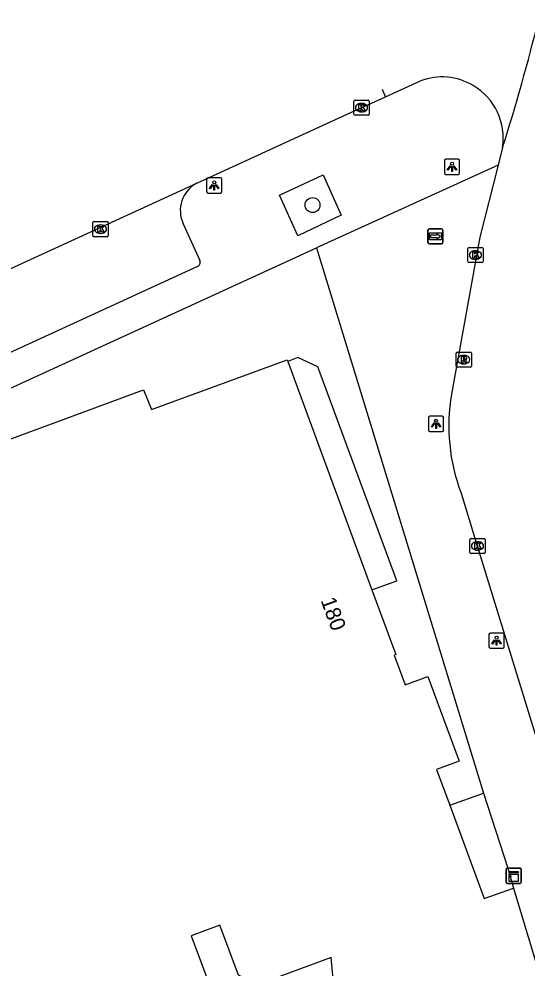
# Model space of a CAD drawing. Extents: x 160806 to 161707, y 383697 to 384148.
# Drawn here: x 161067.6 to 161101, y 383971.5 to 384033.9 of the extents above; entities that cross this region are included whole.
import ezdxf

# ---------------------------------------------------------------- set-up
doc = ezdxf.new("R2010")
doc.units = 0
for name, color, linetype in [('IMGEO_Boom', 7, 'Continuous'), ('IMGEO_Fietspad_gesloten', 7, 'Continuous'), ('IMGEO_Kast', 7, 'Continuous'), ('IMGEO_Kolk', 7, 'Continuous'), ('IMGEO_Lichtpunt', 7, 'Continuous'), ('IMGEO_Pand', 7, 'Continuous'), ('IMGEO_Pand_nummerreeks', 7, 'Continuous'), ('IMGEO_Pand_overbouw', 7, 'Continuous'), ('IMGEO_Rijbaan_lokaal_open', 7, 'Continuous'), ('IMGEO_Rioolput', 7, 'Continuous'), ('IMGEO_Voetpad_open', 7, 'Continuous'), ('IMGEO_Wegwijzer', 7, 'Continuous')]:
    doc.layers.add(name, color=color, linetype=linetype)

msp = doc.modelspace()

# ---------------------------------------------------------------- linework, layer by layer
at = {"layer": 'IMGEO_Boom'}
msp.add_circle((161086.888, 384021.682), 0.489, dxfattribs=at)
at = {"layer": 'IMGEO_Fietspad_gesloten'}
for points in [[(161099.383, 384025.462), (161099.091, 384024.316)], [(161099.091, 384024.316), (161097.884, 384019.582), (161096.025, 384009.243)], [(161096.658, 384002.717), (161097.481, 384000.05), (161112.041, 383952.737)]]:
    msp.add_lwpolyline(points, dxfattribs=at)
msp.add_arc((161108.463, 384007.156), 12.612, 170.47348, 200.60685, dxfattribs=at)
at = {"layer": 'IMGEO_Kast'}
for p, q in [((161099.62, 383977.119), (161099.62, 383977.96)), ((161099.62, 383977.96), (161099.62, 383977.119)), ((161099.695, 383978.044), (161100.536, 383978.044)), ((161100.536, 383978.044), (161099.695, 383978.044)), ((161100.62, 383977.969), (161100.62, 383977.128)), ((161100.62, 383977.128), (161100.62, 383977.969)), ((161100.545, 383977.044), (161099.704, 383977.044)), ((161099.704, 383977.044), (161100.545, 383977.044))]:
    msp.add_line(p, q, dxfattribs=at)
for points in [[(161099.815, 383977.834), (161100.415, 383977.834), (161100.415, 383977.749), (161099.815, 383977.749), (161099.815, 383977.834)], [(161099.815, 383977.659), (161100.415, 383977.659), (161100.415, 383977.17), (161099.815, 383977.17), (161099.815, 383977.659)]]:
    msp.add_lwpolyline(points, dxfattribs=at)
msp.add_circle((161099.899, 383977.508), 0.0377, dxfattribs=at)
for centre, start, end in [((161099.698, 383977.966), 92.4484, 184.28452), ((161099.698, 383977.966), 92.4484, 184.28452), ((161100.542, 383977.966), 2.4484, 94.28452), ((161100.542, 383977.966), 2.4484, 94.28452), ((161099.698, 383977.122), 182.4484, 274.28452), ((161099.698, 383977.122), 182.4484, 274.28452), ((161100.542, 383977.122), 272.4484, 4.28452), ((161100.542, 383977.122), 272.4484, 4.28452)]:
    msp.add_arc(centre, 0.0779, start, end, dxfattribs=at)
at = {"layer": 'IMGEO_Kolk'}
for p, q in [((161089.612, 384027.668), (161089.612, 384028.52)), ((161089.687, 384028.594), (161090.539, 384028.594)), ((161090.1, 384028.374), (161090.125, 384028.374)), ((161090.613, 384028.52), (161090.613, 384027.668)), ((161090.123, 384027.814), (161090.098, 384027.814)), ((161090.539, 384027.594), (161089.687, 384027.594)), ((161072.447, 384019.675), (161072.447, 384020.527)), ((161072.522, 384020.601), (161073.374, 384020.601)), ((161072.935, 384020.381), (161072.96, 384020.381)), ((161073.448, 384020.527), (161073.448, 384019.675)), ((161072.958, 384019.821), (161072.933, 384019.821)), ((161073.374, 384019.601), (161072.522, 384019.601)), ((161097.106, 384017.971), (161097.106, 384018.823)), ((161097.181, 384018.897), (161098.033, 384018.897)), ((161097.594, 384018.677), (161097.619, 384018.677)), ((161098.107, 384018.823), (161098.107, 384017.971)), ((161098.033, 384017.897), (161097.181, 384017.897)), ((161097.617, 384018.117), (161097.592, 384018.117)), ((161097.239, 383998.825), (161097.239, 383999.677)), ((161097.314, 383999.751), (161098.166, 383999.751)), ((161098.24, 383999.677), (161098.24, 383998.825)), ((161097.727, 383999.531), (161097.752, 383999.531)), ((161098.166, 383998.751), (161097.314, 383998.751)), ((161097.75, 383998.971), (161097.725, 383998.971))]:
    msp.add_line(p, q, dxfattribs=at)
for points in [[(161089.612, 384027.668), (161089.612, 384028.52)], [(161089.687, 384028.594), (161090.539, 384028.594)], [(161090.613, 384028.52), (161090.613, 384027.668)], [(161089.933, 384028.294), (161090.056, 384028.294), (161090.056, 384028.143), (161090.186, 384028.294), (161090.35, 384028.294), (161090.204, 384028.143), (161090.357, 384027.894), (161090.205, 384027.894), (161090.12, 384028.058), (161090.056, 384027.991), (161090.056, 384027.894), (161089.933, 384027.894), (161089.933, 384028.294)], [(161090.539, 384027.594), (161089.687, 384027.594)], [(161072.447, 384019.675), (161072.447, 384020.527)], [(161072.522, 384020.601), (161073.374, 384020.601)], [(161072.768, 384020.301), (161072.891, 384020.301), (161072.891, 384020.15), (161073.021, 384020.301), (161073.185, 384020.301), (161073.039, 384020.15), (161073.192, 384019.901), (161073.04, 384019.901), (161072.955, 384020.065), (161072.891, 384019.998), (161072.891, 384019.901), (161072.768, 384019.901), (161072.768, 384020.301)], [(161073.448, 384020.527), (161073.448, 384019.675)], [(161073.374, 384019.601), (161072.522, 384019.601)], [(161097.106, 384017.971), (161097.106, 384018.823)], [(161097.181, 384018.897), (161098.033, 384018.897)], [(161097.427, 384018.597), (161097.55, 384018.597), (161097.55, 384018.446), (161097.68, 384018.597), (161097.844, 384018.597), (161097.698, 384018.446), (161097.851, 384018.197), (161097.699, 384018.197), (161097.614, 384018.361), (161097.55, 384018.294), (161097.55, 384018.197), (161097.427, 384018.197), (161097.427, 384018.597)], [(161098.107, 384018.823), (161098.107, 384017.971)], [(161098.033, 384017.897), (161097.181, 384017.897)], [(161097.239, 383998.825), (161097.239, 383999.677)], [(161097.314, 383999.751), (161098.166, 383999.751)], [(161098.24, 383999.677), (161098.24, 383998.825)], [(161097.56, 383999.451), (161097.683, 383999.451), (161097.683, 383999.3), (161097.813, 383999.451), (161097.977, 383999.451), (161097.831, 383999.3), (161097.984, 383999.051), (161097.832, 383999.051), (161097.747, 383999.215), (161097.683, 383999.148), (161097.683, 383999.051), (161097.56, 383999.051), (161097.56, 383999.451)], [(161098.166, 383998.751), (161097.314, 383998.751)]]:
    msp.add_lwpolyline(points, dxfattribs=at)
for centre, start, end in [((161089.689, 384028.518), 91.55205, 178.44795), ((161089.689, 384028.518), 91.55205, 178.44795), ((161090.537, 384028.518), 1.55205, 88.44795), ((161090.537, 384028.518), 1.55205, 88.44795), ((161089.689, 384027.67), 181.55205, 268.44795), ((161089.689, 384027.67), 181.55205, 268.44795), ((161090.537, 384027.67), 271.55205, 358.44795), ((161090.537, 384027.67), 271.55205, 358.44795), ((161072.524, 384020.525), 91.55205, 178.44795), ((161072.524, 384020.525), 91.55205, 178.44795), ((161073.372, 384020.525), 1.55205, 88.44795), ((161073.372, 384020.525), 1.55205, 88.44795), ((161072.524, 384019.677), 181.55205, 268.44795), ((161072.524, 384019.677), 181.55205, 268.44795), ((161073.372, 384019.677), 271.55205, 358.44795), ((161073.372, 384019.677), 271.55205, 358.44795), ((161097.183, 384018.821), 91.55205, 178.44795), ((161097.183, 384018.821), 91.55205, 178.44795), ((161098.031, 384018.821), 1.55205, 88.44795), ((161098.031, 384018.821), 1.55205, 88.44795), ((161097.183, 384017.973), 181.55205, 268.44795), ((161097.183, 384017.973), 181.55205, 268.44795), ((161098.031, 384017.973), 271.55205, 358.44795), ((161098.031, 384017.973), 271.55205, 358.44795), ((161097.316, 383999.675), 91.55205, 178.44795), ((161097.316, 383999.675), 91.55205, 178.44795), ((161098.164, 383999.675), 1.55205, 88.44795), ((161098.164, 383999.675), 1.55205, 88.44795), ((161097.316, 383998.827), 181.55205, 268.44795), ((161097.316, 383998.827), 181.55205, 268.44795), ((161098.164, 383998.827), 271.55205, 358.44795), ((161098.164, 383998.827), 271.55205, 358.44795)]:
    msp.add_arc(centre, 0.0765, start, end, dxfattribs=at)
for centre, major_axis, ratio, start_param, end_param in [((161090.099, 384028.094), (-0.387, 0.002), 0.722429, 4.712389, 7.853982), ((161090.124, 384028.094), (-0.39, 0.002), 0.717154, 1.570796, 4.712389), ((161072.934, 384020.101), (-0.387, 0.002), 0.722429, 4.712389, 7.853982), ((161072.959, 384020.101), (-0.39, 0.002), 0.717154, 1.570796, 4.712389), ((161097.593, 384018.397), (-0.387, 0.002), 0.722429, 4.712389, 7.853982), ((161097.618, 384018.397), (-0.39, 0.002), 0.717154, 1.570796, 4.712389), ((161097.726, 383999.251), (-0.387, 0.002), 0.722429, 4.712389, 7.853982), ((161097.751, 383999.251), (-0.39, 0.002), 0.717154, 1.570796, 4.712389)]:
    msp.add_ellipse(centre, major_axis=major_axis, ratio=ratio, start_param=start_param, end_param=end_param, dxfattribs=at)
at = {"layer": 'IMGEO_Lichtpunt'}
for p, q in [((161096.469, 384024.702), (161095.661, 384024.702)), ((161096.469, 384024.702), (161095.661, 384024.702)), ((161095.567, 384024.607), (161095.567, 384023.8)), ((161095.567, 384024.607), (161095.567, 384023.8)), ((161096.563, 384023.8), (161096.563, 384024.607)), ((161096.563, 384023.8), (161096.563, 384024.607)), ((161079.925, 384023.378), (161079.925, 384022.571)), ((161079.925, 384023.378), (161079.925, 384022.571)), ((161080.827, 384023.473), (161080.019, 384023.473)), ((161080.827, 384023.473), (161080.019, 384023.473)), ((161080.921, 384022.571), (161080.921, 384023.378)), ((161080.921, 384022.571), (161080.921, 384023.378)), ((161095.661, 384023.706), (161096.469, 384023.706)), ((161095.661, 384023.706), (161096.469, 384023.706)), ((161080.019, 384022.477), (161080.827, 384022.477)), ((161080.019, 384022.477), (161080.827, 384022.477)), ((161095.419, 384007.782), (161094.611, 384007.782)), ((161095.419, 384007.782), (161094.611, 384007.782)), ((161094.517, 384007.687), (161094.517, 384006.88)), ((161094.517, 384007.687), (161094.517, 384006.88)), ((161095.513, 384006.88), (161095.513, 384007.687)), ((161095.513, 384006.88), (161095.513, 384007.687)), ((161094.611, 384006.786), (161095.419, 384006.786)), ((161094.611, 384006.786), (161095.419, 384006.786)), ((161098.493, 383993.419), (161098.493, 383992.612)), ((161098.493, 383993.419), (161098.493, 383992.612)), ((161099.395, 383993.514), (161098.587, 383993.514)), ((161099.395, 383993.514), (161098.587, 383993.514)), ((161099.489, 383992.612), (161099.489, 383993.419)), ((161099.489, 383992.612), (161099.489, 383993.419)), ((161098.587, 383992.518), (161099.395, 383992.518)), ((161098.587, 383992.518), (161099.395, 383992.518))]:
    msp.add_line(p, q, dxfattribs=at)
for points in [[(161095.941, 384024.271), (161095.98, 384024.243), (161095.792, 384023.981), (161095.754, 384024.008), (161095.941, 384024.271)], [(161096.043, 384024.223), (161096.09, 384024.223), (161096.09, 384023.901), (161096.043, 384023.901), (161096.043, 384024.223)], [(161096.153, 384024.243), (161096.191, 384024.27), (161096.378, 384024.008), (161096.339, 384023.98), (161096.153, 384024.243)], [(161080.299, 384023.042), (161080.338, 384023.014), (161080.15, 384022.752), (161080.112, 384022.779), (161080.299, 384023.042)], [(161080.401, 384022.994), (161080.448, 384022.994), (161080.448, 384022.672), (161080.401, 384022.672), (161080.401, 384022.994)], [(161080.511, 384023.014), (161080.549, 384023.041), (161080.736, 384022.779), (161080.697, 384022.751), (161080.511, 384023.014)], [(161094.891, 384007.351), (161094.93, 384007.323), (161094.742, 384007.061), (161094.704, 384007.088), (161094.891, 384007.351)], [(161094.993, 384007.303), (161095.04, 384007.303), (161095.04, 384006.981), (161094.993, 384006.981), (161094.993, 384007.303)], [(161095.103, 384007.323), (161095.141, 384007.35), (161095.328, 384007.088), (161095.289, 384007.06), (161095.103, 384007.323)], [(161098.867, 383993.083), (161098.906, 383993.055), (161098.718, 383992.793), (161098.68, 383992.82), (161098.867, 383993.083)], [(161098.969, 383993.035), (161099.016, 383993.035), (161099.016, 383992.713), (161098.969, 383992.713), (161098.969, 383993.035)], [(161099.079, 383993.055), (161099.117, 383993.082), (161099.304, 383992.82), (161099.265, 383992.792), (161099.079, 383993.055)]]:
    msp.add_lwpolyline(points, dxfattribs=at)
for centre in [(161096.066, 384024.405), (161080.424, 384023.176), (161095.016, 384007.485), (161098.992, 383993.217)]:
    msp.add_circle(centre, 0.0994, dxfattribs=at)
for centre, start, end in [((161095.661, 384024.607), 90, 180), ((161095.661, 384024.607), 90, 180), ((161096.469, 384024.607), 0, 90), ((161096.469, 384024.607), 0, 90), ((161080.019, 384023.378), 90, 180), ((161080.019, 384023.378), 90, 180), ((161080.827, 384023.378), 0, 90), ((161080.827, 384023.378), 0, 90), ((161095.661, 384023.8), 180, 270), ((161095.661, 384023.8), 180, 270), ((161096.469, 384023.8), 270, 0), ((161096.469, 384023.8), 270, 360), ((161080.019, 384022.571), 180, 270), ((161080.019, 384022.571), 180, 270), ((161080.827, 384022.571), 270, 0), ((161080.827, 384022.571), 270, 360), ((161094.611, 384007.687), 90, 180), ((161094.611, 384007.687), 90, 180), ((161095.419, 384007.687), 0, 90), ((161095.419, 384007.687), 0, 90), ((161094.611, 384006.88), 180, 270), ((161094.611, 384006.88), 180, 270), ((161095.419, 384006.88), 270, 0), ((161095.419, 384006.88), 270, 360), ((161098.587, 383993.419), 90, 180), ((161098.587, 383993.419), 90, 180), ((161099.395, 383993.419), 0, 90), ((161099.395, 383993.419), 0, 90), ((161098.587, 383992.612), 180, 270), ((161098.587, 383992.612), 180, 270), ((161099.395, 383992.612), 270, 0), ((161099.395, 383992.612), 270, 360)]:
    msp.add_arc(centre, 0.0946, start, end, dxfattribs=at)
at = {"layer": 'IMGEO_Pand'}
for points in [[(161046.766, 383994.877), (161049.694, 383995.956), (161048.417, 383999.403), (161075.766, 384009.535), (161076.291, 384008.231), (161085.223, 384011.506), (161085.268, 384011.384), (161090.795, 383996.359), (161092.359, 383992.107), (161092.264, 383992.069), (161092.972, 383990.116), (161094.462, 383990.653), (161096.529, 383985.078), (161095.052, 383984.53), (161095.914, 383982.188)], [(161095.914, 383982.188), (161098.17, 383976.057), (161100.111, 383976.738)], [(161100.111, 383976.738), (161107.531, 383952.042), (161107.6, 383951.813)], [(161106.884, 383947.107), (161097.811, 383943.794), (161096.394, 383947.689), (161093.935, 383946.784), (161089.243, 383959.541), (161088.989, 383960.21), (161089.4, 383960.366), (161088.341, 383960.814), (161085.868, 383967.537), (161088.671, 383968.566), (161088.381, 383969.366), (161088.121, 383972.173), (161083.322, 383970.394), (161082.015, 383971.009), (161080.801, 383974.286), (161078.917, 383973.592), (161080.52, 383969.246), (161079.25, 383966.494), (161061.198, 383959.507), (161058.517, 383960.756), (161055.383, 383959.639), (161052.414, 383967.479), (161050.66, 383972.267), (161051.661, 383972.634)]]:
    msp.add_lwpolyline(points, dxfattribs=at)
at = {"layer": 'IMGEO_Pand_overbouw'}
msp.add_lwpolyline([(161085.268, 384011.384), (161090.795, 383996.359), (161092.428, 383996.953), (161087.235, 384011.031), (161085.929, 384011.642)], close=True, dxfattribs=at)
at = {"layer": 'IMGEO_Rijbaan_lokaal_open'}
for points in [[(161091.686, 384028.817), (161093.984, 384029.859)], [(161091.686, 384028.817), (161091.48, 384029.287)], [(161079.27, 384023.126), (161089.159, 384027.656), (161091.686, 384028.817)], [(161046.44, 384008.045), (161079.27, 384023.126)]]:
    msp.add_lwpolyline(points, dxfattribs=at)
for centre, radius, start, end in [((160967.798, 384067.156), 138.032, 342.41873, 346.07153), ((161095.4, 384026.086), 4.03, 59.23998, 110.57029), ((161095.4, 384026.084), 4.031, 351.12055, 59.25199)]:
    msp.add_arc(centre, radius, start, end, dxfattribs=at)
at = {"layer": 'IMGEO_Rioolput'}
for p, q in [((161096.334, 384011.086), (161096.334, 384011.938)), ((161096.409, 384012.012), (161097.261, 384012.012)), ((161096.822, 384011.792), (161096.847, 384011.792)), ((161097.335, 384011.938), (161097.335, 384011.086)), ((161097.261, 384011.012), (161096.409, 384011.012)), ((161096.845, 384011.232), (161096.82, 384011.232))]:
    msp.add_line(p, q, dxfattribs=at)
for points in [[(161096.334, 384011.086), (161096.334, 384011.938)], [(161096.409, 384012.012), (161097.261, 384012.012)], [(161096.923, 384011.71), (161096.671, 384011.712), (161096.671, 384011.312)], [(161096.849, 384011.631), (161096.795, 384011.631), (161096.795, 384011.55)], [(161096.795, 384011.55), (161096.847, 384011.55)], [(161097.335, 384011.938), (161097.335, 384011.086)], [(161097.261, 384011.012), (161096.409, 384011.012)], [(161096.671, 384011.312), (161096.795, 384011.312), (161096.795, 384011.474), (161096.806, 384011.474)], [(161096.853, 384011.445), (161096.924, 384011.312), (161097.064, 384011.312), (161096.999, 384011.438)]]:
    msp.add_lwpolyline(points, dxfattribs=at)
for centre, radius, start, end in [((161096.411, 384011.936), 0.0765, 91.55205, 178.44795), ((161096.411, 384011.936), 0.0765, 91.55205, 178.44795), ((161096.831, 384011.739), 0.19, 274.7715, 282.96867), ((161096.855, 384011.535), 0.0964, 77.00612, 93.18647), ((161096.869, 384011.592), 0.0378, 276.66336, 79.67722), ((161096.922, 384011.6), 0.109, 350.36119, 89.41601), ((161096.92, 384011.6), 0.112, 277.58423, 350.98172), ((161097.259, 384011.936), 0.0765, 1.55205, 88.44795), ((161097.259, 384011.936), 0.0765, 1.55205, 88.44795), ((161096.411, 384011.088), 0.0765, 181.55205, 268.44795), ((161096.411, 384011.088), 0.0765, 181.55205, 268.44795), ((161096.805, 384011.421), 0.0533, 26.02933, 88.69889), ((161096.904, 384011.385), 0.108, 29.51342, 73.79051), ((161097.259, 384011.088), 0.0765, 271.55205, 358.44795), ((161097.259, 384011.088), 0.0765, 271.55205, 358.44795)]:
    msp.add_arc(centre, radius, start, end, dxfattribs=at)
for centre, major_axis, ratio, start_param, end_param in [((161096.821, 384011.512), (-0.387, 0.002), 0.722429, 4.712389, 7.853982), ((161096.846, 384011.512), (-0.39, 0.002), 0.717154, 1.570796, 4.712389)]:
    msp.add_ellipse(centre, major_axis=major_axis, ratio=ratio, start_param=start_param, end_param=end_param, dxfattribs=at)
at = {"layer": 'IMGEO_Voetpad_open'}
for points in [[(161099.091, 384024.316), (161087.151, 384018.873)], [(161084.712, 384022.329), (161087.594, 384023.673), (161088.777, 384021.012), (161085.92, 384019.663), (161084.712, 384022.329)], [(161078.39, 384020.455), (161079.469, 384018.029)], [(161044.796, 383999.32), (161045.113, 383999.3), (161047.022, 384000.146), (161046.899, 384000.438), (161052.328, 384002.909), (161087.151, 384018.873)], [(161087.151, 384018.873), (161098.143, 383982.971)], [(161079.313, 384017.633), (161050.292, 384004.312)], [(161095.914, 383982.188), (161098.143, 383982.971)], [(161098.143, 383982.971), (161099.73, 383978.043), (161100.111, 383976.738)]]:
    msp.add_lwpolyline(points, dxfattribs=at)
for centre, radius, start, end in [((161080.233, 384021.328), 2.04, 118.18629, 205.34326), ((161079.213, 384017.901), 0.286, 290.51859, 26.47854)]:
    msp.add_arc(centre, radius, start, end, dxfattribs=at)
at = {"layer": 'IMGEO_Wegwijzer'}
for p, q in [((161094.479, 384019.223), (161094.479, 384020.023)), ((161094.479, 384020.023), (161094.479, 384019.223)), ((161094.579, 384020.123), (161095.369, 384020.123)), ((161095.369, 384020.123), (161094.579, 384020.123)), ((161095.469, 384020.023), (161095.469, 384019.223)), ((161095.469, 384019.223), (161095.469, 384020.023)), ((161095.369, 384019.123), (161094.579, 384019.123)), ((161094.579, 384019.123), (161095.369, 384019.123))]:
    msp.add_line(p, q, dxfattribs=at)
for points in [[(161094.58, 384019.855), (161095.368, 384019.855), (161095.368, 384019.391), (161094.58, 384019.391), (161094.58, 384019.855)], [(161094.645, 384019.707), (161094.645, 384019.623), (161094.645, 384019.539), (161095.056, 384019.539), (161095.056, 384019.456), (161095.303, 384019.623), (161095.056, 384019.79), (161095.056, 384019.707), (161094.645, 384019.707)]]:
    msp.add_lwpolyline(points, dxfattribs=at)
for centre, start, end in [((161094.579, 384020.023), 90, 180), ((161094.579, 384020.023), 90, 180), ((161095.369, 384020.023), 0, 90), ((161095.369, 384020.023), 360, 90), ((161094.579, 384019.223), 180, 270), ((161094.579, 384019.223), 180, 270), ((161095.369, 384019.223), 270, 0), ((161095.369, 384019.223), 270, 0)]:
    msp.add_arc(centre, 0.1, start, end, dxfattribs=at)

# ---------------------------------------------------------------- texts
at = {"layer": 'IMGEO_Pand_nummerreeks'}
msp.add_text('180', height=1, rotation=290.31687, dxfattribs=at).set_placement((161087.412, 383995.668))

doc.saveas('drawing.dxf')
